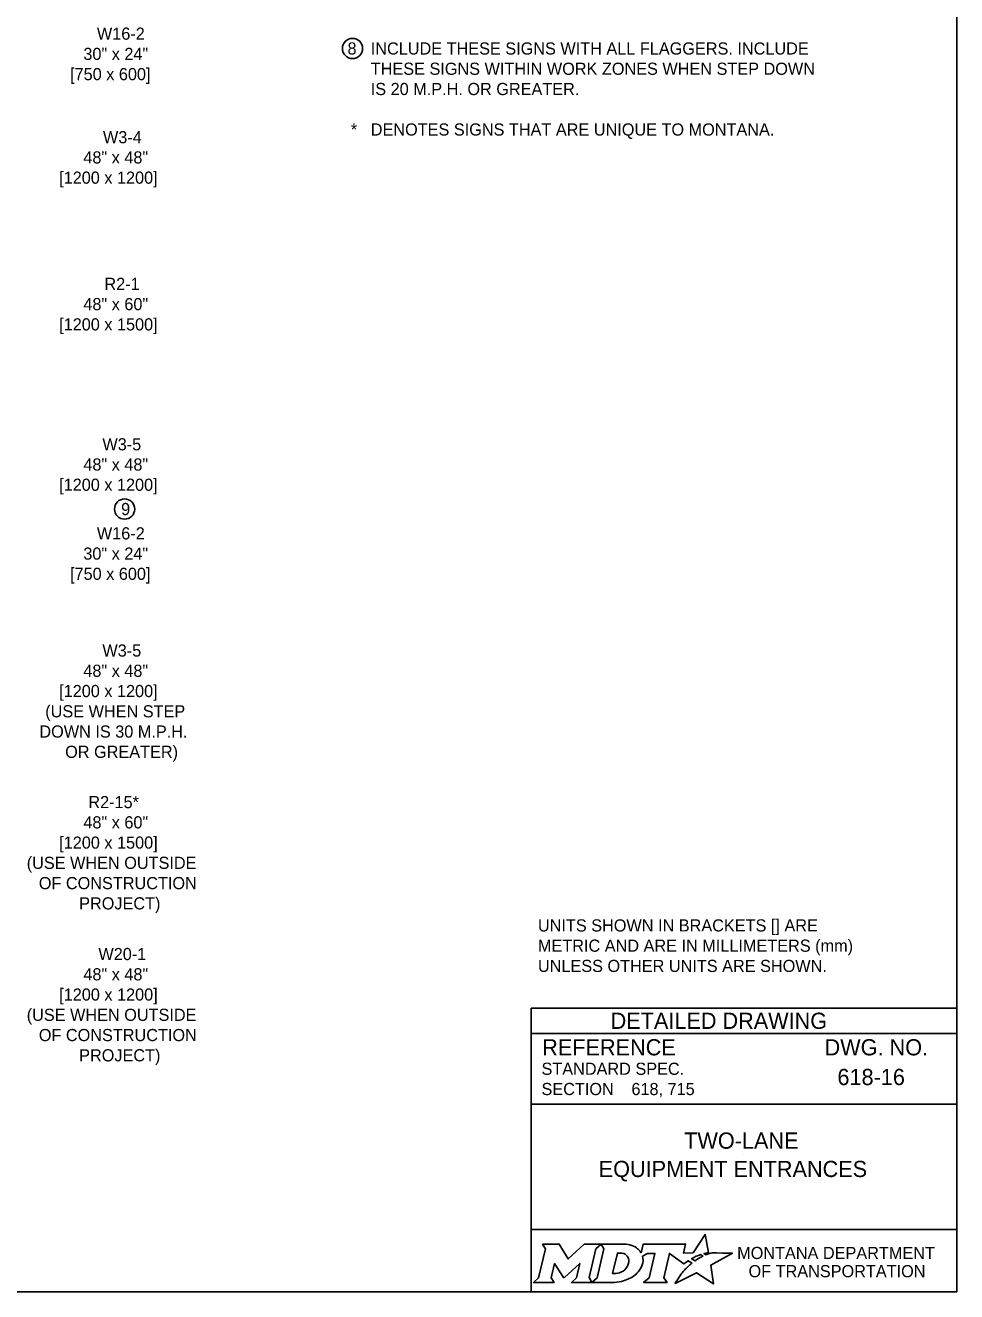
# Model space of a CAD drawing. Extents: x 49991.4 to 50021, y 49987.6 to 50011.4.
# Drawn here: x 50004.02 to 50008.61, y 50000.06 to 50006.31 of the extents above; entities that cross this region are included whole.
import ezdxf

# ---------------------------------------------------------------- set-up
doc = ezdxf.new("R2010")
doc.units = 0
doc.layers.add('Level 1', color=7, linetype='Continuous')
doc.layers.add('Level 2', color=7, linetype='Continuous')

msp = doc.modelspace()

# ---------------------------------------------------------------- linework, layer by layer
at = {"layer": 'Level 1'}
msp.add_lwpolyline([(50008.6146, 50011.2628), (50000.3356, 50011.2628), (50000.3356, 50000.0624), (50008.6146, 50000.0624)], close=True, dxfattribs=at)
at = {"layer": 'Level 2'}
for p, q in [((50008.6146, 50001.4624), (50006.5146, 50001.4624)), ((50006.5146, 50001.4624), (50006.5146, 50000.0624)), ((50008.6146, 50001.3374), (50006.5146, 50001.3374)), ((50008.2507, 50001.1223), (50008.2507, 50001.1223)), ((50007.0089, 50001.0629), (50007.0089, 50001.0629)), ((50008.6146, 50000.9874), (50006.5146, 50000.9874)), ((50007.5646, 50000.7383), (50007.5646, 50000.7383)), ((50008.6146, 50000.3693), (50006.5146, 50000.3693))]:
    msp.add_line(p, q, dxfattribs=at)
for points in [[(50007.3771, 50000.2447), (50007.3668, 50000.2503), (50007.3784, 50000.2531), (50007.39, 50000.2551), (50007.3726, 50000.3452), (50007.3131, 50000.2539), (50007.2658, 50000.2532), (50007.2761, 50000.2973), (50007.0669, 50000.2974), (50007.0568, 50000.2549), (50007.051, 50000.2632)], [(50006.5701, 50000.2974), (50006.5842, 50000.274), (50006.5507, 50000.1307), (50006.525, 50000.1082), (50006.6266, 50000.1082), (50006.6131, 50000.131), (50006.6293, 50000.2011), (50006.673, 50000.1321), (50006.6783, 50000.1321), (50006.7534, 50000.2016), (50006.737, 50000.1305), (50006.7123, 50000.1085), (50006.8139, 50000.1085), (50006.8001, 50000.1318), (50006.8333, 50000.2742)], [(50006.8333, 50000.2742), (50006.8586, 50000.2974), (50006.7762, 50000.2974), (50006.6966, 50000.2244), (50006.6521, 50000.2971), (50006.5701, 50000.2974)], [(50006.9722, 50000.2974), (50006.8586, 50000.2974), (50006.8733, 50000.2745), (50006.8394, 50000.1307), (50006.8139, 50000.1085), (50006.9245, 50000.1085)], [(50006.9962, 50000.2107), (50006.995, 50000.2026), (50006.9918, 50000.1933), (50006.9876, 50000.1851), (50006.982, 50000.1776), (50006.9755, 50000.1707), (50006.9676, 50000.1644), (50006.9593, 50000.1597), (50006.9502, 50000.1558), (50006.9411, 50000.1535), (50006.9319, 50000.1526), (50006.916, 50000.1526), (50006.9396, 50000.2526), (50006.9556, 50000.2526), (50006.9632, 50000.252), (50006.9708, 50000.2501), (50006.9774, 50000.2471), (50006.9835, 50000.2429), (50006.9883, 50000.2379), (50006.992, 50000.2319), (50006.9947, 50000.2257), (50006.9963, 50000.2183), (50006.9963, 50000.2153), (50006.9962, 50000.2107)], [(50007.0636, 50000.2383), (50007.0882, 50000.2514), (50007.1251, 50000.2514), (50007.0965, 50000.1309), (50007.069, 50000.1082), (50007.1852, 50000.1082), (50007.1682, 50000.1311), (50007.1964, 50000.2513), (50007.2677, 50000.1996), (50007.2888, 50000.2147), (50007.3085, 50000.2038)], [(50007.2527, 50000.1479), (50007.2374, 50000.1235), (50007.2327, 50000.116), (50007.2269, 50000.1074), (50007.2246, 50000.1031), (50007.3299, 50000.1562), (50007.4138, 50000.1011), (50007.4007, 50000.1938), (50007.5076, 50000.2522), (50007.4583, 50000.253), (50007.4282, 50000.2534), (50007.4074, 50000.2537), (50007.4006, 50000.2522), (50007.3957, 50000.251), (50007.3873, 50000.2487), (50007.3771, 50000.2447)], [(50007.3267, 50000.2171), (50007.3243, 50000.2154), (50007.306, 50000.225), (50007.3163, 50000.2307), (50007.3204, 50000.2329), (50007.329, 50000.2369), (50007.3347, 50000.2395), (50007.3426, 50000.2425), (50007.3499, 50000.2452), (50007.3617, 50000.2378), (50007.3577, 50000.2357), (50007.3531, 50000.2332), (50007.3489, 50000.231), (50007.3439, 50000.2281), (50007.342, 50000.227), (50007.3393, 50000.2254), (50007.3368, 50000.224), (50007.3345, 50000.2224), (50007.3319, 50000.2206), (50007.3292, 50000.2188), (50007.3267, 50000.2171)], [(50006.9702, 50000.1158), (50006.9786, 50000.1184), (50006.9916, 50000.1238), (50007.012, 50000.1348)], [(50007.2666, 50000.164), (50007.2666, 50000.164)]]:
    msp.add_lwpolyline(points, dxfattribs=at)
for centre in [(50005.6319, 50006.2003), (50005.6319, 50006.2003), (50004.5066, 50003.9264)]:
    msp.add_circle(centre, 0.05, dxfattribs=at)
for centre, radius, start, end in [((50006.9513, 50000.2363), 0.1183, 300.91025, 339.13831), ((50006.9953, 50000.219), 0.0709, 339.53292, 15.85821)]:
    msp.add_arc(centre, radius, start, end, dxfattribs=at)
for centre, major_axis, ratio, start_param, end_param in [((50006.9701, 50000.25), (0.0834, -0.0037), 0.568097, 0.61298, 1.570796), ((50007.0257, 50000.2573), (0.0361, -0.0295), 0.469099, 1.225588, 1.570796), ((50007.2764, 50000.1742), (-0.0098, -0.0102), 0.016458, 3.141593, 6.279097), ((50007.2974, 50000.1941), (-0.0112, -0.0097), 0.021651, 3.157348, 6.283185), ((50007.2597, 50000.1559), (-0.00694, -0.00806), 0.008222, 0, 3.137361), ((50006.9248, 50000.2568), (0, 0.1484), 0.987302, 3.139398, 3.456847)]:
    msp.add_ellipse(centre, major_axis=major_axis, ratio=ratio, start_param=start_param, end_param=end_param, dxfattribs=at)

# ---------------------------------------------------------------- texts
for s, height, p in [('W16-2', 0.06, (50004.3698, 50006.2436)), ('30" x 24"', 0.06, (50004.303, 50006.1436)), ('8', 0.06, (50005.607, 50006.1703)), ('INCLUDE THESE SIGNS WITH ALL FLAGGERS. INCLUDE ', 0.06, (50005.7219, 50006.1703)), ('THESE SIGNS WITHIN WORK ZONES WHEN STEP DOWN ', 0.06, (50005.7219, 50006.0703)), ('[750 x 600]', 0.06, (50004.2374, 50006.0437)), ('IS 20 M.P.H. OR GREATER.', 0.06, (50005.7219, 50005.9703)), ('*', 0.06, (50005.6234, 50005.7703)), ('DENOTES SIGNS THAT ARE UNIQUE TO MONTANA.', 0.06, (50005.7219, 50005.7703)), ('W3-4', 0.06, (50004.3997, 50005.7325)), ('48" x 48"', 0.06, (50004.3029, 50005.6325)), ('[1200 x 1200]', 0.06, (50004.1834, 50005.5326)), ('R2-1', 0.06, (50004.407, 50005.0081)), ('48" x 60"', 0.06, (50004.3029, 50004.9081)), ('[1200 x 1500]', 0.06, (50004.1834, 50004.8082)), ('W3-5', 0.05999, (50004.3969, 50004.2162)), ('48" x 48"', 0.05999, (50004.3029, 50004.1163)), ('[1200 x 1200]', 0.059993, (50004.1834, 50004.0164)), ('9', 0.06, (50004.4893, 50003.8964)), ('W16-2', 0.05999, (50004.3696, 50003.7764)), ('30" x 24"', 0.05999, (50004.3028, 50003.6765)), ('[750 x 600]', 0.059993, (50004.2372, 50003.5766)), ('W3-5', 0.06, (50004.3969, 50003.1979)), ('48" x 48"', 0.06, (50004.3029, 50003.0979)), ('[1200 x 1200]', 0.06, (50004.1834, 50002.9979)), ('(USE WHEN STEP', 0.06, (50004.1148, 50002.8979)), ('DOWN IS 30 M.P.H.', 0.06, (50004.0859, 50002.7979)), ('OR GREATER)', 0.06, (50004.2131, 50002.6979)), ('R2-15*', 0.06, (50004.3276, 50002.4496)), ('48" x 60"', 0.06, (50004.303, 50002.3496)), ('[1200 x 1500]', 0.06, (50004.1836, 50002.2496)), ('(USE WHEN OUTSIDE', 0.06, (50004.0233, 50002.1496)), ('OF CONSTRUCTION', 0.06, (50004.083, 50002.0496)), ('PROJECT)', 0.06, (50004.2822, 50001.9496)), ('UNITS SHOWN IN BRACKETS [] ARE ', 0.06, (50006.5473, 50001.8407)), ('W20-1', 0.06, (50004.3772, 50001.6994)), ('METRIC AND ARE IN MILLIMETERS (mm) ', 0.06, (50006.5473, 50001.7407)), ('UNLESS OTHER UNITS ARE SHOWN.', 0.06, (50006.5473, 50001.6407)), ('48" x 48"', 0.06, (50004.303, 50001.5994)), ('[1200 x 1200]', 0.06, (50004.1836, 50001.4994)), ('(USE WHEN OUTSIDE', 0.06, (50004.0233, 50001.3994)), ('DETAILED DRAWING', 0.0799, (50006.9063, 50001.3599)), ('OF CONSTRUCTION', 0.06, (50004.083, 50001.2994)), ('REFERENCE', 0.08, (50006.5682, 50001.229)), ('DWG. NO.', 0.08, (50007.9624, 50001.229)), ('PROJECT)', 0.06, (50004.2822, 50001.1994)), ('STANDARD SPEC.', 0.06, (50006.5649, 50001.133)), ('618-16', 0.08, (50008.0259, 50001.0823)), ('SECTION', 0.06, (50006.5649, 50001.033)), ('618, 715', 0.06, (50007.0089, 50001.0329)), ('TWO-LANE', 0.08, (50007.2692, 50000.7683)), ('EQUIPMENT ENTRANCES', 0.08, (50006.8472, 50000.6283)), ('MONTANA DEPARTMENT', 0.06, (50007.5308, 50000.2236)), ('OF TRANSPORTATION', 0.06, (50007.587, 50000.1336))]:
    msp.add_text(s, height=height, dxfattribs=at).set_placement(p)

doc.saveas('drawing.dxf')
